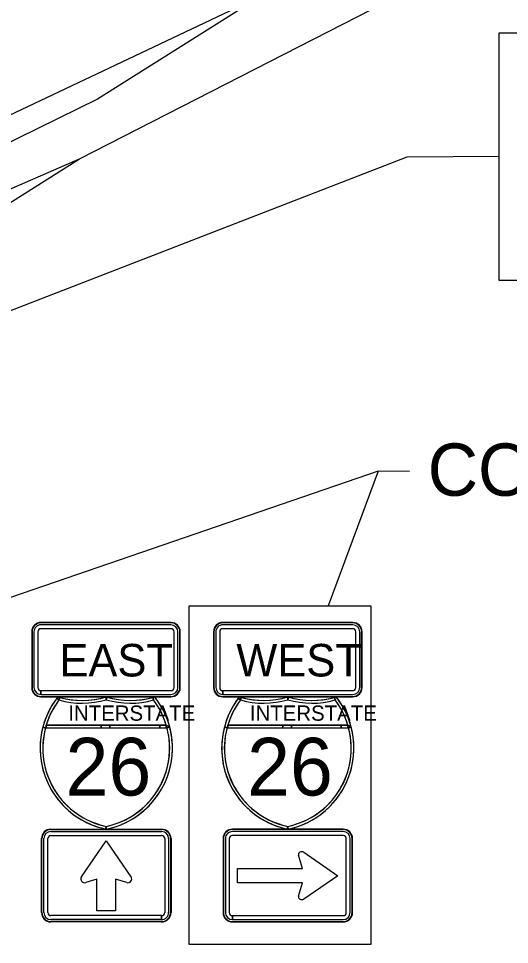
# Model space of a CAD drawing. Extents: x 886234 to 968767, y 455416 to 684046.
# Drawn here: x 909996 to 911583, y 490248 to 493238 of the extents above; entities that cross this region are included whole.
import ezdxf

# ---------------------------------------------------------------- set-up
doc = ezdxf.new("R2010")
doc.units = 0
for name, color, linetype in [('TC CONSTRUCTION PROPOSED ROADWAY SHADE', 7, 'Continuous'), ('TC DEV SIGN BLACK 239', 7, 'Continuous'), ('TC DEV SIGN BLACK ZERO', 7, 'Continuous'), ('TC DEV SIGN WHITE', 7, 'Continuous'), ('TC LABEL TEXT', 7, 'Continuous')]:
    doc.layers.add(name, color=color, linetype=linetype)

msp = doc.modelspace()

# ---------------------------------------------------------------- linework, layer by layer
at = {"layer": 'TC CONSTRUCTION PROPOSED ROADWAY SHADE'}
msp.add_lwpolyline([(910546.9, 491341), (911134.6, 491341), (911134.6, 490247.9), (910546.9, 490247.9)], close=True, dxfattribs=at)
at = {"layer": 'TC DEV SIGN BLACK 239'}
for p, q in [((910488.5, 491280.1), (910068.4, 491280.1)), ((911076.2, 491280.1), (910656.1, 491280.1)), ((910045.9, 491257.6), (910045.9, 491077.6)), ((910058.4, 491257.6), (910058.4, 491077.6)), ((910488.5, 491267.6), (910068.4, 491267.6)), ((910498.5, 491077.6), (910498.5, 491257.6)), ((910511, 491077.6), (910511, 491257.6)), ((910633.6, 491257.6), (910633.6, 491077.6)), ((910646.1, 491257.6), (910646.1, 491077.6)), ((911076.2, 491267.6), (910656.1, 491267.6)), ((911086.2, 491077.6), (911086.2, 491257.6)), ((911098.7, 491077.6), (911098.7, 491257.6)), ((910068.4, 491055.1), (910068.4, 491067.6)), ((910068.5, 491067.6), (910488.5, 491067.6)), ((910068.5, 491067.6), (910068.5, 491055.1)), ((910068.5, 491055.1), (910488.5, 491055.1)), ((910656.1, 491055.1), (910656.1, 491067.6)), ((910656.2, 491067.6), (911076.2, 491067.6)), ((910656.2, 491067.6), (910656.2, 491055.1)), ((910656.2, 491055.1), (911076.2, 491055.1)), ((910100.5, 490612.5), (910458.3, 490612.5)), ((910100.5, 490599.8), (910458.3, 490599.8)), ((911045, 490612.5), (910687.3, 490612.5)), ((911045, 490599.8), (910687.3, 490599.8)), ((910077.7, 490351.1), (910077.7, 490589.7)), ((910090.4, 490351.1), (910090.4, 490589.7)), ((910468.4, 490589.7), (910468.4, 490351.1)), ((910481.1, 490589.7), (910481.1, 490351.1)), ((910664.4, 490589.7), (910664.4, 490351.1)), ((910677.1, 490589.7), (910677.1, 490351.1)), ((911055.2, 490351.1), (911055.2, 490589.7)), ((911067.9, 490351.1), (911067.9, 490589.7)), ((910913.6, 490493.3), (910901.2, 490536.4)), ((910918.4, 490545.7), (911028.4, 490469.9)), ((910703.7, 490447.3), (910703.7, 490493.3)), ((910703.7, 490493.3), (910913.6, 490493.3)), ((910913.6, 490447.3), (910703.7, 490447.3)), ((910901.2, 490403.4), (910913.6, 490447.3)), ((911028.4, 490469.9), (910918.4, 490394.2)), ((910458.2, 490341), (910100.5, 490341)), ((910458.2, 490328.3), (910100.5, 490328.3)), ((910458.2, 490341), (910458.2, 490328.3)), ((910458.3, 490328.3), (910458.3, 490341)), ((910687.3, 490328.3), (910687.3, 490341)), ((910687.4, 490341), (911045, 490341)), ((910687.4, 490341), (910687.4, 490328.3)), ((910687.4, 490328.3), (911045, 490328.3))]:
    msp.add_line(p, q, dxfattribs=at)
for points in [[(910199.3, 490466.1), (910279.4, 490582.8), (910359.4, 490466.1)], [(910199.3, 490466.1), (910279.4, 490582.8), (910359.4, 490466.1)], [(910199.3, 490466.1), (910279.4, 490582.8), (910359.4, 490466.1)], [(910249, 490356.7), (910249, 490459), (910213, 490447.7)], [(910249, 490356.7), (910249, 490459), (910213, 490447.7)], [(910249, 490356.7), (910249, 490459), (910213, 490447.7)], [(910345.7, 490447.7), (910309.8, 490459), (910309.8, 490356.7), (910249, 490356.7)], [(910345.7, 490447.7), (910309.8, 490459), (910309.8, 490356.7), (910249, 490356.7)], [(910345.7, 490447.7), (910309.8, 490459), (910309.8, 490356.7), (910249, 490356.7)]]:
    msp.add_lwpolyline(points, dxfattribs=at)
for centre, start, end in [((910209.4, 490459.2), 145.5508, 287.601), ((910209.4, 490459.2), 145.5508, 287.601), ((910209.4, 490459.2), 145.5508, 287.601), ((910349.4, 490459.2), 252.399, 34.4492), ((910349.4, 490459.2), 252.399, 34.4492), ((910349.4, 490459.2), 252.399, 34.4492)]:
    msp.add_arc(centre, 12.2, start, end, dxfattribs=at)
for centre, major_axis, ratio, start_param, end_param in [((910068.4, 491257.6), (22.5, 0), 0.999865, 1.570796, 3.141593), ((910488.5, 491257.6), (22.5, 0), 0.999865, 0, 1.570796), ((910656.1, 491257.6), (22.5, 0), 0.999865, 1.570796, 3.141593), ((911076.2, 491257.6), (22.5, 0), 0.999865, 0, 1.570796), ((910068.4, 491257.6), (10, 0), 0.999865, 1.570796, 3.141593), ((910488.5, 491257.6), (10, 0), 0.999865, 0, 1.570796), ((910656.1, 491257.6), (10, 0), 0.999865, 1.570796, 3.141593), ((911076.2, 491257.6), (10, 0), 0.999865, 0, 1.570796), ((910068.4, 491077.6), (22.5, 0), 0.999865, 3.141593, 4.712389), ((910068.4, 491077.6), (10, 0), 0.999865, 3.141593, 4.712389), ((910488.5, 491077.6), (22.5, 0), 0.999865, 4.712389, 6.283185), ((910488.5, 491077.6), (10, 0), 0.999865, 4.712389, 6.283185), ((910656.1, 491077.6), (22.5, 0), 0.999865, 3.141593, 4.712389), ((910656.1, 491077.6), (10, 0), 0.999865, 3.141593, 4.712389), ((911076.2, 491077.6), (22.5, 0), 0.999865, 4.712389, 6.283185), ((911076.2, 491077.6), (10, 0), 0.999865, 4.712389, 6.283185), ((910100.5, 490589.7), (-22.8, 0), 0.999865, 4.712389, 6.283185), ((910100.5, 490589.7), (-10.1, 0), 0.999865, 4.712389, 6.283185), ((910458.3, 490589.7), (-22.8, 0), 0.999865, 3.141593, 4.712389), ((910458.3, 490589.7), (-10.1, 0), 0.999865, 3.141593, 4.712389), ((910687.3, 490589.7), (22.8, 0), 0.999865, 1.570796, 3.141593), ((910687.3, 490589.7), (10.1, 0), 0.999865, 1.570796, 3.141593), ((911045, 490589.7), (22.8, 0), 0.999865, 0, 1.570796), ((911045, 490589.7), (10.1, 0), 0.999865, 0, 1.570796), ((910912, 490538.9), (11.3, 0), 0.720018, 0.96961, 3.452569), ((910912, 490400.9), (11.3, 0), 0.720018, 2.830617, 5.313577), ((910100.5, 490351.1), (-22.8, 0), 0.999865, 0, 1.570796), ((910100.5, 490351.1), (-10.1, 0), 0.999865, 0, 1.570796), ((910458.3, 490351.1), (-22.8, 0), 0.999865, 1.570796, 3.141593), ((910458.3, 490351.1), (-10.1, 0), 0.999865, 1.570796, 3.141593), ((910687.3, 490351.1), (22.8, 0), 0.999865, 3.141593, 4.712389), ((910687.3, 490351.1), (10.1, 0), 0.999865, 3.141593, 4.712389), ((911045, 490351.1), (22.8, 0), 0.999865, 4.712389, 6.283185), ((911045, 490351.1), (10.1, 0), 0.999865, 4.712389, 6.283185)]:
    msp.add_ellipse(centre, major_axis=major_axis, ratio=ratio, start_param=start_param, end_param=end_param, dxfattribs=at)
at = {"layer": 'TC DEV SIGN BLACK ZERO'}
for p, q in [((910488.5, 491287.6), (910068.4, 491287.6)), ((910068.4, 491286.4), (910068.4, 491286.4)), ((910488.5, 491286.3), (910068.4, 491286.4)), ((910488.5, 491286.3), (910488.5, 491286.4)), ((911076.2, 491287.6), (910656.1, 491287.6)), ((910656.1, 491286.4), (910656.1, 491286.4)), ((911076.2, 491286.3), (910656.1, 491286.4)), ((911076.2, 491286.3), (911076.2, 491286.4)), ((910038.4, 491257.6), (910038.4, 491077.6)), ((910039.7, 491257.6), (910039.7, 491077.6)), ((910039.7, 491257.6), (910039.7, 491257.6)), ((910517.2, 491257.6), (910517.2, 491257.6)), ((910517.2, 491077.6), (910517.2, 491257.6)), ((910518.5, 491077.6), (910518.5, 491257.6)), ((910626.1, 491257.6), (910626.1, 491077.6)), ((910627.4, 491257.6), (910627.4, 491077.6)), ((910627.4, 491257.6), (910627.4, 491257.6)), ((911104.9, 491257.6), (911104.9, 491257.6)), ((911104.9, 491077.6), (911104.9, 491257.6)), ((911106.2, 491077.6), (911106.2, 491257.6)), ((910039.7, 491077.6), (910039.7, 491077.6)), ((910517.2, 491077.6), (910517.2, 491077.6)), ((910627.4, 491077.6), (910627.4, 491077.6)), ((911104.9, 491077.6), (911104.9, 491077.6)), ((910068.4, 491047.6), (910068.4, 491048.9)), ((910068.4, 491048.9), (910068.4, 491048.9)), ((910068.4, 491048.9), (910488.5, 491048.9)), ((910068.4, 491048.9), (910068.4, 491047.6)), ((910068.4, 491047.6), (910488.5, 491047.6)), ((910126.6, 491037.4), (910129, 491045.9)), ((910279.6, 491038.3), (910279.4, 491047.6)), ((910279.6, 491039), (910279.4, 491047.6)), ((910429.8, 491045.9), (910432.2, 491037.4)), ((910488.5, 491048.9), (910488.5, 491048.9)), ((910656.1, 491047.6), (910656.1, 491048.9)), ((910656.1, 491048.9), (910656.1, 491048.9)), ((910656.1, 491048.9), (911076.2, 491048.9)), ((910656.1, 491048.9), (910656.1, 491047.6)), ((910656.1, 491047.6), (911076.2, 491047.6)), ((910713.3, 491037.4), (910715.7, 491045.9)), ((910866.4, 491038.3), (910866.2, 491047.6)), ((910866.4, 491039), (910866.2, 491047.6)), ((911016.6, 491045.9), (911019, 491037.4)), ((911076.2, 491048.9), (911076.2, 491048.9)), ((910085.5, 490956.4), (910473.2, 490956.4)), ((910263.1, 490956.4), (910085.5, 490956.4)), ((910291.2, 490956.4), (910263.1, 490956.4)), ((910452.3, 490956.4), (910291.2, 490956.4)), ((910473.2, 490956.4), (910452.3, 490956.4)), ((910484.4, 490949.8), (910473.2, 490956.4)), ((910672.3, 490956.4), (911060, 490956.4)), ((910849.8, 490956.4), (910672.3, 490956.4)), ((910878, 490956.4), (910849.8, 490956.4)), ((911039, 490956.4), (910878, 490956.4)), ((911060, 490956.4), (911039, 490956.4)), ((911071.1, 490949.8), (911060, 490956.4)), ((910083, 490947.5), (910475.8, 490947.5)), ((910083, 490947.5), (910085.5, 490947.5)), ((910085.5, 490947.5), (910263.1, 490947.5)), ((910263.1, 490947.5), (910291.2, 490947.5)), ((910291.2, 490947.5), (910452.3, 490947.5)), ((910452.3, 490947.5), (910473.2, 490947.5)), ((910475.6, 490948.2), (910473.2, 490947.5)), ((910473.2, 490947.5), (910475.8, 490947.5)), ((910669.8, 490947.5), (911062.5, 490947.5)), ((910669.8, 490947.5), (910672.3, 490947.5)), ((910672.3, 490947.5), (910849.8, 490947.5)), ((910849.8, 490947.5), (910878, 490947.5)), ((910878, 490947.5), (911039, 490947.5)), ((911039, 490947.5), (911060, 490947.5)), ((911062.3, 490948.2), (911060, 490947.5)), ((911060, 490947.5), (911062.5, 490947.5)), ((910065.6, 490883.2), (910065.6, 490880.6)), ((910493.1, 490880.5), (910493.1, 490883.3)), ((910652.4, 490883.2), (910652.4, 490880.6)), ((911079.9, 490880.5), (911079.9, 490883.3)), ((910100.5, 490620.1), (910458.3, 490620.1)), ((910100.5, 490618.8), (910458.3, 490618.8)), ((910100.5, 490618.8), (910100.5, 490618.8)), ((910458.3, 490618.8), (910458.3, 490618.8)), ((911045, 490620.1), (910687.3, 490620.1)), ((910687.3, 490618.8), (910687.3, 490618.8)), ((911045, 490618.8), (910687.3, 490618.8)), ((911045, 490618.8), (911045, 490618.8)), ((910070.1, 490351.1), (910070.1, 490589.7)), ((910071.3, 490589.7), (910071.3, 490589.7)), ((910071.3, 490351.1), (910071.3, 490589.7)), ((910487.4, 490589.7), (910487.5, 490351.1)), ((910487.4, 490589.7), (910487.4, 490589.7)), ((910488.7, 490589.7), (910488.7, 490351.1)), ((910656.8, 490589.7), (910656.8, 490351.1)), ((910658.1, 490589.7), (910658.1, 490351.1)), ((910658.1, 490589.7), (910658.1, 490589.7)), ((911074.2, 490589.7), (911074.2, 490589.7)), ((911074.2, 490351.1), (911074.2, 490589.7)), ((911075.5, 490351.1), (911075.5, 490589.7)), ((910071.3, 490351.1), (910071.4, 490351.1)), ((910487.4, 490351.1), (910487.5, 490351.1)), ((910658.1, 490351.1), (910658.1, 490351.1)), ((911074.2, 490351.1), (911074.2, 490351.1)), ((910100.5, 490322), (910100.5, 490322)), ((910458.3, 490322), (910100.5, 490322)), ((910458.3, 490320.7), (910100.5, 490320.7)), ((910458.3, 490320.7), (910458.3, 490322)), ((910458.3, 490322), (910458.3, 490322)), ((910458.3, 490322), (910458.3, 490320.7)), ((910687.3, 490320.7), (910687.3, 490322)), ((910687.3, 490322), (910687.3, 490322)), ((910687.3, 490322), (911045, 490322)), ((910687.3, 490322), (910687.3, 490320.7)), ((910687.3, 490320.7), (911045, 490320.7)), ((911045, 490322), (911045, 490322))]:
    msp.add_line(p, q, dxfattribs=at)
for points in [[(910119.4, 491042.7), (910126.6, 491037.4)], [(910126.6, 491037.4), (910119.4, 491042.7)], [(910123.2, 491047.6), (910123.2, 491047.6), (910123.2, 491047.6)], [(910129, 491045.9), (910126.6, 491037.4)], [(910279.6, 491047.5), (910279.6, 491039), (910282.1, 491046.8)], [(910282.1, 491046.8), (910279.6, 491038.3)], [(910432.2, 491037.4), (910429.8, 491045.9)], [(910435.6, 491047.6), (910435.5, 491047.6), (910435.5, 491047.6)], [(910706.2, 491042.7), (910713.3, 491037.4)], [(910713.3, 491037.4), (910706.2, 491042.7)], [(910710, 491047.6), (910710, 491047.6), (910710, 491047.6)], [(910715.7, 491045.9), (910713.3, 491037.4)], [(910866.4, 491047.5), (910866.4, 491039), (910868.9, 491046.8)], [(910868.9, 491046.8), (910866.4, 491038.3)], [(911019, 491037.4), (911016.6, 491045.9)], [(911022.3, 491047.6), (911022.3, 491047.6), (911022.3, 491047.6)], [(910279.4, 491038.3), (910279.6, 491039)], [(910866.2, 491038.3), (910866.4, 491039)], [(910085.5, 490956.4), (910085.5, 490947.5)], [(910085.5, 490947.5), (910085.5, 490956.4)], [(910263.1, 490947.5), (910263.1, 490956.4)], [(910263.1, 490956.4), (910263.1, 490947.5)], [(910291.2, 490956.4), (910291.2, 490947.5)], [(910291.2, 490947.5), (910291.2, 490956.4)], [(910452.3, 490947.5), (910452.3, 490956.4)], [(910452.3, 490956.4), (910452.3, 490947.5)], [(910473.2, 490956.4), (910484.4, 490949.8)], [(910473.2, 490947.5), (910473.2, 490956.4)], [(910473.2, 490956.4), (910473.2, 490947.5), (910475.6, 490948.2), (910473.2, 490956.4)], [(910672.3, 490956.4), (910672.3, 490947.5)], [(910672.3, 490947.5), (910672.3, 490956.4)], [(910849.8, 490947.5), (910849.8, 490956.4)], [(910849.8, 490956.4), (910849.8, 490947.5)], [(910878, 490956.4), (910878, 490947.5)], [(910878, 490947.5), (910878, 490956.4)], [(911039, 490947.5), (911039, 490956.4)], [(911039, 490956.4), (911039, 490947.5)], [(911060, 490956.4), (911071.1, 490949.8)], [(911060, 490947.5), (911060, 490956.4)], [(911060, 490956.4), (911060, 490947.5), (911062.3, 490948.2), (911060, 490956.4)], [(910074.4, 490949.8), (910083, 490947.5)], [(910083, 490947.5), (910074.4, 490949.8)], [(910475.8, 490947.5), (910475.6, 490948.2)], [(910484.4, 490949.8), (910475.8, 490947.5)], [(910475.8, 490947.5), (910484.4, 490949.8)], [(910661.2, 490949.8), (910669.8, 490947.5)], [(910669.8, 490947.5), (910661.2, 490949.8)], [(911062.5, 490947.5), (911062.3, 490948.2)], [(911071.1, 490949.8), (911062.5, 490947.5)], [(911062.5, 490947.5), (911071.1, 490949.8)], [(910277.5, 490620.5), (910279.4, 490629.2)], [(910279.4, 490629.2), (910279.4, 490620.1)], [(910864.3, 490620.5), (910866.2, 490629.2)], [(910866.2, 490629.2), (910866.2, 490620.1)]]:
    msp.add_lwpolyline(points, dxfattribs=at)
for centre, radius, start, end in [((910332.8, 490881.9), 267.2, 141.6693, 258.4631), ((910332.8, 490881.9), 267.2, 142.9968, 165.2769), ((910332.8, 490881.9), 267.2, 141.6709, 142.9968), ((910201.3, 491303.1), 267.2, 253.0062, 286.9901), ((910201.3, 491303.1), 267.2, 253.0099, 254.2907), ((910201.3, 491303.1), 267.2, 254.2907, 286.9893), ((910357.5, 491303.1), 267.2, 253.0099, 286.9938), ((910226, 490881.9), 267.2, 281.5369, 38.3307), ((910357.5, 491303.1), 267.2, 253.0588, 253.6206), ((910357.5, 491303.1), 267.2, 253.6206, 285.7093), ((910357.5, 491303.1), 267.2, 285.7093, 286.9901), ((910226, 490881.9), 267.2, 14.7231, 38.3291), ((910919.6, 490881.9), 267.2, 141.6693, 258.4631), ((910919.6, 490881.9), 267.2, 142.9968, 165.2769), ((910919.6, 490881.9), 267.2, 141.6709, 142.9968), ((910788.1, 491303.1), 267.2, 253.0062, 286.9901), ((910788.1, 491303.1), 267.2, 253.0099, 254.2907), ((910788.1, 491303.1), 267.2, 254.2907, 286.9893), ((910944.2, 491303.1), 267.2, 253.0099, 286.9938), ((910812.7, 490881.9), 267.2, 281.5369, 38.3307), ((910944.2, 491303.1), 267.2, 253.0588, 253.6206), ((910944.2, 491303.1), 267.2, 253.6206, 285.7093), ((910944.2, 491303.1), 267.2, 285.7093, 286.9901), ((910812.7, 490881.9), 267.2, 14.7231, 38.3291), ((910332.8, 490881.9), 258.3, 142.9968, 258.0595), ((910332.8, 490881.9), 258.3, 142.9968, 165.2769), ((910201.3, 491303.1), 276.1, 254.2907, 286.4259), ((910201.3, 491303.1), 276.1, 254.2907, 286.4259), ((910357.5, 491303.1), 276.1, 253.5741, 285.7093), ((910226, 490881.9), 258.3, 281.9405, 37.0032), ((910357.6, 491302.7), 275.7, 253.5731, 285.7093), ((910226, 490881.9), 258.3, 16.7759, 37.0032), ((910919.6, 490881.9), 258.3, 142.9968, 258.0595), ((910919.6, 490881.9), 258.3, 142.9968, 165.2769), ((910788.1, 491303.1), 276.1, 254.2907, 286.4259), ((910788.1, 491303.1), 276.1, 254.2907, 286.4259), ((910944.2, 491303.1), 276.1, 253.5741, 285.7093), ((910812.7, 490881.9), 258.3, 281.9405, 37.0032), ((910944.3, 491302.7), 275.7, 253.5731, 285.7093), ((910812.7, 490881.9), 258.3, 16.7759, 37.0032), ((910332.8, 490881.9), 258.3, 163.2241, 165.2769), ((910226, 490881.9), 258.3, 14.7231, 16.7759), ((910919.6, 490881.9), 258.3, 163.2241, 165.2769), ((910812.7, 490881.9), 258.3, 14.7231, 16.7759), ((910332.8, 490881.9), 267.2, 165.2769, 179.7177), ((910331.6, 490881.1), 257.3, 165.0438, 258.3001), ((910227.2, 490881.1), 257.3, 281.7196, 14.964), ((910226, 490881.9), 267.2, 0.2997, 14.7231), ((910919.6, 490881.9), 267.2, 165.2769, 179.7177), ((910918.3, 490881.1), 257.3, 165.0438, 258.3001), ((910814, 490881.1), 257.3, 281.7196, 14.964), ((910812.7, 490881.9), 267.2, 0.2997, 14.7231), ((910332.8, 490881.9), 267.2, 180.2823, 258.0591), ((910226, 490881.9), 267.2, 281.537, 359.7003), ((910919.6, 490881.9), 267.2, 180.2823, 258.0591), ((910812.7, 490881.9), 267.2, 281.537, 359.7003), ((910226, 490881.9), 258.3, 281.9405, 281.9604), ((910812.7, 490881.9), 258.3, 281.9405, 281.9604)]:
    msp.add_arc(centre, radius, start, end, dxfattribs=at)
for centre, major_axis, start_param, end_param in [((910068.4, 491257.6), (30, 0), 1.570796, 3.141593), ((910068.4, 491257.6), (28.8, 0), 1.570796, 3.141593), ((910488.5, 491257.6), (30, 0), 0, 1.570796), ((910488.5, 491257.6), (28.8, 0), 0, 1.570796), ((910656.1, 491257.6), (30, 0), 1.570796, 3.141593), ((910656.1, 491257.6), (28.8, 0), 1.570796, 3.141593), ((911076.2, 491257.6), (30, 0), 0, 1.570796), ((911076.2, 491257.6), (28.8, 0), 0, 1.570796), ((910068.4, 491077.6), (30, 0), 3.141593, 4.712389), ((910068.4, 491077.6), (28.8, 0), 3.141593, 4.712389), ((910488.5, 491077.6), (30, 0), 4.712389, 6.283185), ((910488.5, 491077.6), (28.8, 0), 4.712389, 6.283185), ((910656.1, 491077.6), (30, 0), 3.141593, 4.712389), ((910656.1, 491077.6), (28.8, 0), 3.141593, 4.712389), ((911076.2, 491077.6), (30, 0), 4.712389, 6.283185), ((911076.2, 491077.6), (28.8, 0), 4.712389, 6.283185), ((910100.5, 490589.7), (-30.4, 0), 4.712389, 6.283185), ((910100.5, 490589.7), (-29.2, 0), 4.712389, 6.283185), ((910458.3, 490589.7), (-30.4, 0), 3.141593, 4.712389), ((910458.3, 490589.7), (-29.2, 0), 3.141593, 4.712389), ((910687.3, 490589.7), (30.4, 0), 1.570796, 3.141593), ((910687.3, 490589.7), (29.2, 0), 1.570796, 3.141593), ((911045, 490589.7), (30.4, 0), 0, 1.570796), ((911045, 490589.7), (29.2, 0), 0, 1.570796), ((910100.5, 490351.1), (-30.4, 0), 0, 1.570796), ((910100.5, 490351.1), (-29.2, 0), 0, 1.570796), ((910458.3, 490351.1), (-30.4, 0), 1.570796, 3.141593), ((910458.3, 490351.1), (-29.2, 0), 1.570796, 3.141593), ((910687.3, 490351.1), (30.4, 0), 3.141593, 4.712389), ((910687.3, 490351.1), (29.2, 0), 3.141593, 4.712389), ((911045, 490351.1), (30.4, 0), 4.712389, 6.283185), ((911045, 490351.1), (29.2, 0), 4.712389, 6.283185)]:
    msp.add_ellipse(centre, major_axis=major_axis, ratio=0.999865, start_param=start_param, end_param=end_param, dxfattribs=at)
at = {"layer": 'TC DEV SIGN WHITE'}
for p, q in [((910488.5, 491287.6), (910068.4, 491287.6)), ((911076.2, 491287.6), (910656.1, 491287.6)), ((910038.4, 491257.6), (910038.4, 491077.6)), ((910518.5, 491077.6), (910518.5, 491257.6)), ((910626.1, 491257.6), (910626.1, 491077.6)), ((911106.2, 491077.6), (911106.2, 491257.6)), ((910068.4, 491047.6), (910488.5, 491047.6)), ((910656.1, 491047.6), (911076.2, 491047.6)), ((910279.4, 490620.1), (910279.4, 490629.2)), ((910866.2, 490620.1), (910866.2, 490629.2)), ((910100.5, 490620.1), (910458.3, 490620.1)), ((911045, 490620.1), (910687.3, 490620.1)), ((910070.1, 490351.1), (910070.1, 490589.7)), ((910488.7, 490589.7), (910488.7, 490351.1)), ((910656.8, 490589.7), (910656.8, 490351.1)), ((911075.5, 490351.1), (911075.5, 490589.7)), ((910458.3, 490320.7), (910100.5, 490320.7)), ((910687.3, 490320.7), (911045, 490320.7))]:
    msp.add_line(p, q, dxfattribs=at)
for points in [[(910279.4, 490629.2), (910277.5, 490620.5), (910279.4, 490620.1)], [(910866.2, 490629.2), (910864.3, 490620.5), (910866.1, 490620.1)]]:
    msp.add_lwpolyline(points, dxfattribs=at)
for centre, start, end in [((910332.8, 490881.9), 258.458, 258.463), ((910226, 490881.9), 281.5369590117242, 281.53700435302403), ((910919.6, 490881.9), 258.458, 258.463), ((910812.7, 490881.9), 281.5369590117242, 281.53700435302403)]:
    msp.add_arc(centre, 267.2, start, end, dxfattribs=at)
for centre, major_axis, start_param, end_param in [((910068.4, 491257.6), (30, 0), 1.570796, 3.141593), ((910488.5, 491257.6), (30, 0), 0, 1.570796), ((910656.1, 491257.6), (30, 0), 1.570796, 3.141593), ((911076.2, 491257.6), (30, 0), 0, 1.570796), ((910068.4, 491077.6), (30, 0), 3.141593, 4.712389), ((910488.5, 491077.6), (30, 0), 4.712389, 6.283185), ((910656.1, 491077.6), (30, 0), 3.141593, 4.712389), ((911076.2, 491077.6), (30, 0), 4.712389, 6.283185), ((910100.5, 490589.7), (-30.4, 0), 4.712389, 6.283185), ((910458.3, 490589.7), (-30.4, 0), 3.141593, 4.712389), ((910687.3, 490589.7), (30.4, 0), 1.570796, 3.141593), ((911045, 490589.7), (30.4, 0), 0, 1.570796), ((910100.5, 490351.1), (-30.4, 0), 0, 1.570796), ((910458.3, 490351.1), (-30.4, 0), 1.570796, 3.141593), ((910687.3, 490351.1), (30.4, 0), 3.141593, 4.712389), ((911045, 490351.1), (30.4, 0), 4.712389, 6.283185)]:
    msp.add_ellipse(centre, major_axis=major_axis, ratio=0.999865, start_param=start_param, end_param=end_param, dxfattribs=at)
at = {"layer": 'TC LABEL TEXT'}
msp.add_line((911158.4, 491776.7), (910996.4, 491341.6), dxfattribs=at)
for points in [[(910192.5, 492784.2), (911706, 493559)], [(910779.8, 493311.1), (909675.8, 492787.5), (909488.1, 492724.9), (908151.1, 492396.8)], [(910779.8, 493311.1), (910251.2, 492977.9), (909608.1, 492662.5), (909077.9, 492437.9), (908233.2, 492156.1)], [(908268.4, 492056.3), (908503, 492132.6), (908896.1, 492279.4), (909218.7, 492385), (909623.5, 492537.6), (910192.5, 492784.2)], [(911549.5, 492792.2), (911250.6, 492790.5), (908345.1, 491665.6)], [(908347.6, 491824.7), (909799.5, 492537.6), (910192.5, 492784.2)], [(911259, 491775.1), (911158.4, 491776.7), (909902.8, 491345.7)]]:
    msp.add_lwpolyline(points, dxfattribs=at)
for points in [[(911549.5, 493192), (918459, 493192), (918459, 492392.3), (911549.5, 492392.3)], [(910546.9, 491341), (911134.6, 491341), (911134.6, 490247.9), (910546.9, 490247.9)]]:
    msp.add_lwpolyline(points, close=True, dxfattribs=at)

# ---------------------------------------------------------------- texts
at = {"layer": 'TC DEV SIGN BLACK 239'}
for s, p in [('EAST', (910128.1, 491113.3)), ('WEST', (910699.7, 491113.3))]:
    msp.add_text(s, height=105, rotation=360, dxfattribs=at).set_placement(p)
at = {"layer": 'TC DEV SIGN BLACK ZERO'}
for s, height, p in [('INTERSTATE', 49.28, (910156.9, 490970.3)), ('INTERSTATE', 49.28, (910743.7, 490970.3)), ('26', 186.16, (910148, 490728.9)), ('26', 186.16, (910734.8, 490728.9))]:
    msp.add_text(s, height=height, rotation=360, dxfattribs=at).set_placement(p)
at = {"layer": 'TC LABEL TEXT'}
msp.add_text('COVER', height=168.75, dxfattribs=at).set_placement((911318.3, 491696.8))

doc.saveas('drawing.dxf')
